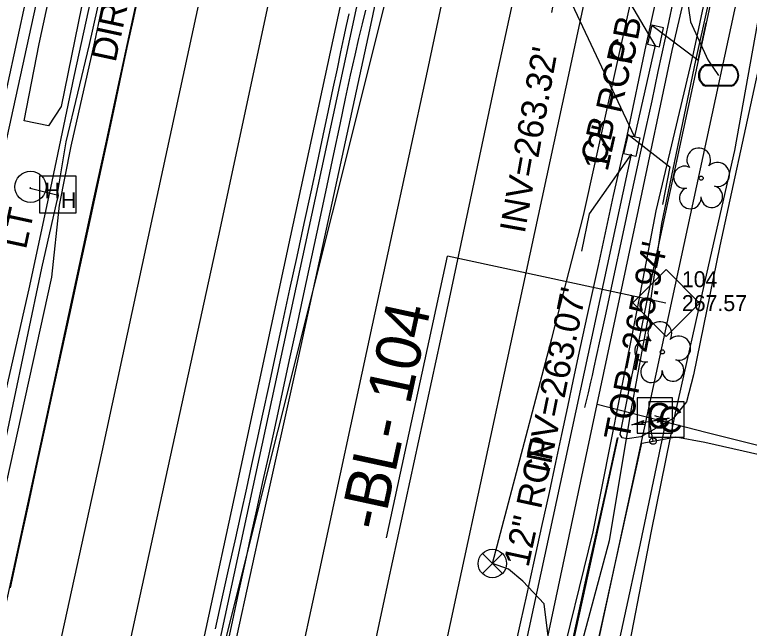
# Model space of a CAD drawing. Extents: x 2100323 to 2109811, y 740376 to 749755.
# Drawn here: x 2106040.1 to 2106155.4, y 743168.3 to 743264.5 of the extents above; entities that cross this region are included whole.
import ezdxf

# ---------------------------------------------------------------- set-up
doc = ezdxf.new("R2010")
doc.units = 0
for name, color, linetype in [('CTL Supplemental Horizontal and Vertical CELL', 7, 'Continuous'), ('CTL Supplemental Horizontal and Vertical Cogo Elevation', 7, 'Continuous'), ('CTL Supplemental Horizontal and Vertical Cogo Number', 7, 'Continuous'), ('Exist Building', 7, 'Continuous'), ('Exist Horizontal Alignment', 7, 'Continuous'), ('Exist Horizontal Baseline Alignment Station Label', 7, 'Continuous'), ('Exist Right of Way Line', 7, 'Continuous'), ('Exist Roads Change in Surface', 7, 'Continuous'), ('Exist Roads Curbs', 7, 'Continuous'), ('Exist Roads EOP', 7, 'Continuous'), ('Exist Roads EOP Other', 7, 'Continuous'), ('Exist Roads EOT', 7, 'Continuous'), ('Exist Structure Minor Catch Basin', 7, 'Continuous'), ('Exist Structure Minor Catch Basin Text', 7, 'Continuous'), ('Exist Structure Minor Catch Basin Top Elevation', 7, 'Continuous'), ('Exist Structure Minor Pipes RCP 12 Inch', 7, 'Continuous'), ('Exist Structure Minor Pipes RCP 12 Inch Invert', 7, 'Continuous'), ('Exist Structure Minor Pipes RCP 12 Inch Leader', 7, 'Continuous'), ('Exist Structure Minor Pipes RCP 12 Inch Text', 7, 'Continuous'), ('Exist Utilities Gas Change of Service SUE CELL', 7, 'Continuous'), ('Exist Utilities Gas UG Line SUE LOS B', 7, 'Continuous'), ('Exist Utilities Gas UG Line SUE LOS C', 7, 'Continuous'), ('Exist Utilities Other Pole CELL', 7, 'Continuous'), ('Exist Utilities Other Pole Text', 7, 'Continuous'), ('Exist Utilities Power Hand Hole CELL', 7, 'Continuous'), ('Exist Utilities Power UG Cable SUE LOS B', 7, 'Continuous'), ('Exist Utilities Telephone UG Conduit SUE LOS B', 7, 'Continuous'), ('Exist Utilities TV Pedestal CELL', 7, 'Continuous'), ('Exist Utilities TV UG Cable SUE LOS B', 7, 'Continuous'), ('Exist Utilities Water Meter CELL', 7, 'Continuous'), ('Exist Utilities Water UG Line SUE LOS B', 7, 'Continuous'), ('Exist Utilities Water UG Line SUE LOS C', 7, 'Continuous'), ('Exist Utilities Water Valve CELL', 7, 'Continuous'), ('Exist Vegetation Hedge Row', 7, 'Continuous'), ('Exist Vegetation Tree CELL', 7, 'Continuous')]:
    doc.layers.add(name, color=color, linetype=linetype)

msp = doc.modelspace()

# ---------------------------------------------------------------- linework, layer by layer
at = {"layer": 'CTL Supplemental Horizontal and Vertical CELL'}
msp.add_line((2106142.34, 743219.3), (2106142.34, 743219.3), dxfattribs=at)
msp.add_lwpolyline([(2106137.13, 743219.32), (2106142.37, 743224.56), (2106147.62, 743219.31), (2106142.38, 743214.07)], close=True, dxfattribs=at)
at = {"layer": 'Exist Building'}
msp.add_lwpolyline([(2106037.99, 743573.24), (2106018.9, 743485.96), (2106017.36, 743486.3), (2105996.61, 743391.41), (2105959.32, 743399.57), (2105929.35, 743262.52), (2106037.5, 743238.87), (2106107.3, 743558.09), (2106037.99, 743573.24)], dxfattribs=at)
at = {"layer": 'Exist Horizontal Alignment'}
msp.add_line((2106017.48, 742912.16), (2106313.31, 744282.7), dxfattribs=at)
at = {"layer": 'Exist Horizontal Baseline Alignment Station Label'}
for p in [(2106098.51, 743182.45), (2106142.34, 743219.3)]:
    msp.add_line(p, (2106108.06, 743226.69), dxfattribs=at)
at = {"layer": 'Exist Right of Way Line'}
for p, q in [((2106074.25, 742899.91), (2106310.88, 743996.15)), ((2105967.64, 742922.92), (2106195.83, 743980.08))]:
    msp.add_line(p, q, dxfattribs=at)
at = {"layer": 'Exist Roads Change in Surface'}
msp.add_lwpolyline([(2106126.61, 743160.71), (2106129.74, 743175), (2106134.86, 743198.21)], dxfattribs=at)
at = {"layer": 'Exist Roads Curbs'}
msp.add_lwpolyline([(2106143.36, 743266.32), (2106142.2, 743260.85), (2106141.09, 743255.65), (2106140.1, 743251.06), (2106139.19, 743246.87), (2106138.1, 743241.86), (2106136.79, 743235.85), (2106135.41, 743229.49), (2106134.1, 743223.4), (2106132.89, 743217.77), (2106131.98, 743213.55), (2106131.4, 743210.9), (2106131.03, 743209.23), (2106130.74, 743207.95), (2106130.5, 743206.92), (2106130.11, 743205.24), (2106129.57, 743202.91)], dxfattribs=at)
at = {"layer": 'Exist Roads EOP'}
for points in [[(2106118.63, 743165.04), (2106119.55, 743169.28), (2106120.49, 743173.46), (2106121.61, 743178.51), (2106122.88, 743184.24), (2106124.04, 743189.57), (2106125.06, 743194.3), (2106126, 743198.7), (2106126.92, 743203.01), (2106127.84, 743207.32), (2106128.89, 743212.18), (2106130.09, 743217.67), (2106131.73, 743225.2), (2106134.11, 743236.16), (2106136.23, 743245.52), (2106139.24, 743259.77), (2106142.15, 743273.03)], [(2106039.48, 743174.63), (2106040.84, 743180.94), (2106042.28, 743187.59), (2106043.67, 743194.05), (2106045.01, 743200.23), (2106046.32, 743206.31), (2106047.67, 743212.47), (2106049.04, 743218.74), (2106050.47, 743225.33), (2106051.97, 743232.27), (2106053.42, 743239.04), (2106054.73, 743245.08), (2106055.88, 743250.44), (2106056.91, 743255.21), (2106057.81, 743259.41), (2106058.71, 743263.59), (2106059.71, 743268.26)], [(2106071.65, 743168.2), (2106072.66, 743172.76), (2106073.69, 743177.43), (2106074.71, 743182.02), (2106075.66, 743186.3), (2106076.55, 743190.29), (2106077.37, 743193.99), (2106078.19, 743197.73), (2106079.09, 743201.85), (2106080.07, 743206.37), (2106081.12, 743211.27), (2106082.22, 743216.37), (2106083.33, 743221.49), (2106084.45, 743226.62), (2106085.57, 743231.77), (2106086.66, 743236.74), (2106087.66, 743241.36), (2106088.57, 743245.62), (2106089.4, 743249.51), (2106090.14, 743253.01), (2106090.79, 743256.08), (2106091.34, 743258.71), (2106091.8, 743260.9), (2106092.21, 743262.83), (2106092.62, 743264.66)], [(2106073.3, 743164.7), (2106074.31, 743169.27), (2106075.33, 743174), (2106076.35, 743178.69), (2106077.31, 743183.13), (2106078.23, 743187.33), (2106079.1, 743191.28), (2106079.95, 743195.12), (2106080.79, 743198.97), (2106081.64, 743202.84), (2106082.48, 743206.72), (2106083.38, 743210.87), (2106084.4, 743215.56), (2106085.53, 743220.78), (2106086.77, 743226.54), (2106088.02, 743232.36), (2106089.17, 743237.75), (2106090.23, 743242.74), (2106091.19, 743247.3), (2106092.06, 743251.42), (2106092.84, 743255.04), (2106093.55, 743258.18), (2106094.16, 743260.83), (2106094.71, 743263.14), (2106095.22, 743265.26)]]:
    msp.add_lwpolyline(points, dxfattribs=at)
at = {"layer": 'Exist Roads EOP Other'}
for points in [[(2105989.88, 742978.1), (2105992.89, 742991.26), (2106005.74, 743051.33), (2106017.11, 743104.36), (2106021.65, 743125.26), (2106026.92, 743151.57), (2106033.25, 743181.45), (2106042.52, 743222), (2106046.03, 743238.36), (2106049.46, 743254.83), (2106054.7, 743278.8), (2106061.75, 743311.36), (2106068.7, 743343.35), (2106074.92, 743372.78), (2106081.36, 743401.84), (2106085.54, 743420.55), (2106091.74, 743449.28), (2106096.24, 743470.29), (2106097.48, 743476.53)], [(2106080.8, 743366.85), (2106079.4, 743360.36), (2106077.85, 743353.14), (2106076.13, 743345.17), (2106074.26, 743336.46), (2106072.23, 743327.02), (2106070.21, 743317.61), (2106068.36, 743309.02), (2106066.69, 743301.24), (2106065.18, 743294.28), (2106063.85, 743288.13), (2106062.56, 743282.15), (2106061.16, 743275.67), (2106059.65, 743268.7), (2106058.04, 743261.24), (2106056.32, 743253.28), (2106054.48, 743244.73), (2106052.47, 743235.47), (2106050.32, 743225.5), (2106048, 743214.83), (2106045.53, 743203.45), (2106043.07, 743192.09), (2106040.77, 743181.48), (2106038.65, 743171.63)], [(2106161.39, 743276.68), (2106156.38, 743253.99), (2106150.81, 743228.26), (2106146.67, 743208.06), (2106145.55, 743203.82), (2106143.48, 743201.21), (2106138.4, 743198.33), (2106136.23, 743197.99), (2106135.49, 743198.14), (2106135.14, 743198.69), (2106140.27, 743224.09), (2106146.56, 743253.22), (2106151.11, 743274.45)], [(2106126.71, 743161.86), (2106129.94, 743176.57), (2106132.91, 743189.76), (2106134.76, 743198.15)]]:
    msp.add_lwpolyline(points, dxfattribs=at)
at = {"layer": 'Exist Roads EOT'}
for points in [[(2106042.22, 743015.09), (2106047.83, 743040.43), (2106053.82, 743067.44), (2106059.54, 743094.14), (2106064.45, 743117.21), (2106069.23, 743140.31), (2106072.98, 743157.65), (2106079.06, 743185.57), (2106084.46, 743209.75), (2106090.21, 743236.18), (2106095.86, 743262.17), (2106102.27, 743292.24), (2106107.53, 743316.8), (2106112.64, 743340.89), (2106118.09, 743366.19), (2106124.09, 743393.83), (2106130.04, 743422.38), (2106135.51, 743447.94), (2106140.44, 743471.17), (2106145.44, 743493.68), (2106154.86, 743537.27), (2106165.29, 743585.16)], [(2106137.18, 743582.93), (2106129.02, 743544.65), (2106120.52, 743506.04), (2106112.02, 743466.55), (2106104.11, 743429.36), (2106095.71, 743390.07), (2106086.87, 743348.78), (2106078.51, 743309.78), (2106070.2, 743271.79), (2106061.76, 743232.89), (2106053.82, 743195.96), (2106045.11, 743156.31), (2106036.83, 743117.88), (2106028.4, 743079), (2106020.18, 743040.87), (2106011.78, 743002.02)], [(2106146.94, 743578.03), (2106138.92, 743540.77), (2106130.66, 743502.58), (2106122.28, 743464.49), (2106113.88, 743424.79), (2106105.83, 743386.93), (2106097.43, 743347.7), (2106089.21, 743309.26), (2106080.88, 743270.71), (2106072.32, 743230.86), (2106063.87, 743192.12), (2106055.42, 743153.43), (2106047.06, 743115.78), (2106038.73, 743077.35), (2106030.31, 743038.03), (2106021.98, 742999.54)], [(2106158.44, 743577.13), (2106150.88, 743543.06), (2106141.86, 743501.64), (2106133.69, 743463.5), (2106125.22, 743424.34), (2106117.02, 743385.24), (2106108.57, 743346.18), (2106100.3, 743308.18), (2106092.15, 743270.35), (2106083.38, 743229.64), (2106074.58, 743188.81), (2106066.53, 743151.58), (2106058.54, 743114.96), (2106050.08, 743075.72), (2106041.09, 743034.02), (2106033.02, 742996.93)], [(2106171.45, 743565.7), (2106162.92, 743526.09), (2106154.45, 743487.7), (2106146.46, 743449.9), (2106138.49, 743412.94), (2106129.21, 743369.77), (2106121.28, 743332.76), (2106113.24, 743295.18), (2106104.84, 743255.68), (2106096.26, 743215.86), (2106087.79, 743176.73), (2106079.4, 743137.92), (2106071.31, 743101.11), (2106063, 743062.7), (2106054.24, 743022.2)], [(2106193.66, 743565.28), (2106185.3, 743526.87), (2106176.78, 743487.84), (2106168.56, 743449.4), (2106160.38, 743411.11), (2106152.2, 743372.73), (2106144.04, 743334.47), (2106135.63, 743295.17), (2106126.64, 743253.17), (2106117.92, 743212.89), (2106109.67, 743174.65), (2106101.11, 743134.7), (2106092.9, 743096.54), (2106084.52, 743058.41), (2106075.56, 743016.95)], [(2106182.44, 743563.86), (2106174.23, 743526.18), (2106165.71, 743486.89), (2106157.44, 743448.87), (2106149.13, 743409.72), (2106140.41, 743369.02), (2106132.02, 743330.94), (2106124, 743292.93), (2106115.66, 743254.49), (2106107.57, 743216.53), (2106098.74, 743175.74), (2106090.58, 743137.61), (2106082.3, 743099.34), (2106073.69, 743059.33), (2106064.38, 743016.38)]]:
    msp.add_lwpolyline(points, dxfattribs=at)
at = {"layer": 'Exist Structure Minor Catch Basin'}
for points in [[(2106141.3, 743259.52), (2106141.95, 743262.49), (2106140.11, 743262.89), (2106139.46, 743259.92)], [(2106138.24, 743245.23), (2106137.59, 743242.32), (2106135.73, 743242.74), (2106136.39, 743245.65)]]:
    msp.add_lwpolyline(points, close=True, dxfattribs=at)
at = {"layer": 'Exist Structure Minor Catch Basin Top Elevation'}
for points in [[(2106140.11, 743262.88), (2106147.4, 743257.4), (2106148.64, 743263.27)], [(2106136.34, 743245.78), (2106142.96, 743240.68), (2106141.8, 743234.79)]]:
    msp.add_lwpolyline(points, dxfattribs=at)
at = {"layer": 'Exist Structure Minor Pipes RCP 12 Inch'}
for p, q in [((2106140.62, 743259.77), (2106137.42, 743245.42)), ((2106136.88, 743242.67), (2106098.45, 743064.44))]:
    msp.add_line(p, q, dxfattribs=at)
at = {"layer": 'Exist Structure Minor Pipes RCP 12 Inch Leader'}
for points in [[(2106137.42, 743245.42), (2106125.46, 743270.8), (2106124.39, 743264.9)], [(2106140.62, 743259.77), (2106136.13, 743267.43), (2106136.47, 743269.02)], [(2106136.88, 743242.67), (2106130.27, 743233.32), (2106129.07, 743227.44)]]:
    msp.add_lwpolyline(points, dxfattribs=at)
at = {"layer": 'Exist Utilities Gas Change of Service SUE CELL'}
for p, q in [((2106142.86, 743201.25), (2106136.99, 743200.2)), ((2106139.77, 743200.7), (2106142.86, 743201.25)), ((2106140.31, 743197.66), (2106139.77, 743200.7)), ((2106140.31, 743197.66), (2106140.31, 743197.66))]:
    msp.add_line(p, q, dxfattribs=at)
for points in [[(2106142.86, 743201.25), (2106140.98, 743200.57), (2106141.33, 743200.98), (2106140.9, 743201.21)], [(2106136.99, 743200.2), (2106138.87, 743200.89), (2106138.51, 743200.47), (2106138.94, 743200.24)]]:
    msp.add_lwpolyline(points, close=True, dxfattribs=at)
msp.add_circle((2106140.31, 743197.66), 0.517, dxfattribs=at)
at = {"layer": 'Exist Utilities Gas UG Line SUE LOS B'}
msp.add_lwpolyline([(2106140.31, 743197.66), (2106143.88, 743198.31), (2106148.46, 743197.48), (2106192.36, 743187.57), (2106207.21, 743185.29), (2106222.26, 743181.85), (2106233.55, 743180.98), (2106241.94, 743181.9), (2106247.4, 743184.25)], dxfattribs=at)
at = {"layer": 'Exist Utilities Gas UG Line SUE LOS C'}
msp.add_lwpolyline([(2106064.67, 742860.19), (2106069.59, 742879.36), (2106086.29, 742957.89), (2106098.56, 743010.84), (2106112.62, 743079.76), (2106138.57, 743197.35), (2106140.31, 743197.66)], dxfattribs=at)
at = {"layer": 'Exist Utilities Other Pole CELL'}
msp.add_circle((2106042.62, 743237.54), 2.46, dxfattribs=at)
at = {"layer": 'Exist Utilities Power Hand Hole CELL'}
msp.add_line((2106046.99, 743236.2), (2106046.99, 743236.2), dxfattribs=at)
msp.add_lwpolyline([(2106044.04, 743233.47), (2106049.79, 743233.47), (2106049.79, 743239.22), (2106044.04, 743239.22), (2106044.04, 743233.47)], dxfattribs=at)
at = {"layer": 'Exist Utilities Power UG Cable SUE LOS B'}
for points in [[(2106046.99, 743236.2), (2106046.92, 743236.77), (2106048.23, 743244.61), (2106051.85, 743259.85), (2106058.03, 743287.41), (2106062.68, 743310.27), (2106066.47, 743326.61), (2106068.59, 743337.33), (2106074.88, 743361.82), (2106076.79, 743376.2), (2106078.79, 743383.74), (2106081.19, 743394.01), (2106081.35, 743394.88), (2106080.32, 743395.02), (2106077.01, 743395.65), (2106076.86, 743395.66)], [(2106078.42, 743380.17), (2106078.04, 743377.85), (2106074.52, 743362.69), (2106069.27, 743337.24), (2106067.38, 743327.27), (2106061.4, 743310.77), (2106058.61, 743288.6), (2106052.66, 743260.3), (2106048.94, 743243.92), (2106047.1, 743234.64), (2106045.92, 743223.36), (2106038.78, 743191.03), (2106034.86, 743175.39), (2106030.52, 743155.65), (2106029.65, 743154.26)], [(2106094.23, 743016.65), (2106098.81, 743040.21), (2106103.37, 743060.13), (2106106.75, 743074.8), (2106112.98, 743104.04), (2106117.89, 743128.72), (2106120.32, 743138.55), (2106121.45, 743145.59), (2106122.31, 743148.82), (2106125.2, 743160.21), (2106130.9, 743183.42), (2106137.89, 743218.46), (2106140.82, 743233.8), (2106146.65, 743258.46), (2106151.21, 743279.92), (2106156.39, 743299.99), (2106156.84, 743301.79)], [(2106128, 743161.62), (2106133.5, 743182.08), (2106136.92, 743202.71), (2106139.59, 743217.17), (2106141.7, 743231.8), (2106147.04, 743257.37), (2106150.69, 743273.82), (2106152.6, 743281.09), (2106154.87, 743290.32), (2106155.9, 743291.18), (2106155.23, 743291.59), (2106155.71, 743295.79), (2106156.71, 743299.84), (2106156.84, 743301.79), (2106157.69, 743301.38), (2106160.23, 743300.55), (2106162.62, 743297.85)], [(2106127.24, 743143.85), (2106128.32, 743143.14), (2106130.45, 743145.28), (2106132.42, 743151.09), (2106135.43, 743159.46), (2106140.07, 743183.51), (2106143.83, 743202.07), (2106148.81, 743224.15), (2106153.14, 743243.22), (2106157.68, 743268.66), (2106160.13, 743282.88), (2106161.79, 743295.06), (2106162.62, 743297.85)], [(2106021.82, 743118.35), (2106021.8, 743119.15), (2106026.94, 743145.86), (2106029.69, 743157.25), (2106033.91, 743175.01), (2106037.29, 743191.19), (2106044.4, 743224.78), (2106046.82, 743235.41), (2106046.99, 743236.2), (2106046.14, 743236.38), (2106042.59, 743237.29), (2106042.64, 743237.49)]]:
    msp.add_lwpolyline(points, dxfattribs=at)
at = {"layer": 'Exist Utilities Telephone UG Conduit SUE LOS B'}
for points in [[(2106086.38, 742995.86), (2106097.58, 743046.43), (2106104.1, 743075.32), (2106115.52, 743129.19), (2106122.57, 743161.02), (2106131.54, 743203.47), (2106138.01, 743233.94), (2106143.33, 743258.94), (2106148.33, 743280.51)], [(2106131.54, 743203.47), (2106148.81, 743199.01), (2106192.13, 743188.16), (2106207.68, 743184.44), (2106211.82, 743184.37), (2106213.24, 743186.14), (2106214.3, 743188.57), (2106214.93, 743191.07)]]:
    msp.add_lwpolyline(points, dxfattribs=at)
at = {"layer": 'Exist Utilities TV Pedestal CELL'}
for p, q in [((2106140.59, 743201.64), (2106140.59, 743201.64)), ((2106142.43, 743201.05), (2106142.43, 743201.05))]:
    msp.add_line(p, q, dxfattribs=at)
for points in [[(2106137.81, 743198.87), (2106143.36, 743198.87), (2106143.36, 743204.42), (2106137.81, 743204.42), (2106137.81, 743198.87)], [(2106139.66, 743198.28), (2106145.21, 743198.28), (2106145.21, 743203.83), (2106139.66, 743203.83), (2106139.66, 743198.28)]]:
    msp.add_lwpolyline(points, dxfattribs=at)
at = {"layer": 'Exist Utilities TV UG Cable SUE LOS B'}
msp.add_lwpolyline([(2106104.33, 743022.68), (2106109.86, 743044.21), (2106114.03, 743071.01), (2106120.9, 743102.04), (2106125.34, 743120.47), (2106131.18, 743142.67), (2106133.66, 743159.9), (2106138.14, 743180.61), (2106142.43, 743201.05), (2106140.59, 743201.64)], dxfattribs=at)
at = {"layer": 'Exist Utilities Water Meter CELL'}
msp.add_line((2106150.61, 743255.02), (2106150.61, 743255.02), dxfattribs=at)
for points in [[(2106148.57, 743256.72), (2106152.65, 743256.72)], [(2106148.57, 743256.58), (2106152.65, 743256.58)], [(2106152.65, 743253.45), (2106148.55, 743253.45)], [(2106152.65, 743253.32), (2106148.55, 743253.32)]]:
    msp.add_lwpolyline(points, dxfattribs=at)
for centre, radius, start, end in [((2106149.3, 743255.01), 1.86, 113.178, 245.9794), ((2106149.31, 743255.01), 1.73, 115.3009, 243.7824), ((2106151.9, 743255.02), 1.86, 293.6483, 66.3084), ((2106151.92, 743255.02), 1.73, 295.1272, 64.8728)]:
    msp.add_arc(centre, radius, start, end, dxfattribs=at)
at = {"layer": 'Exist Utilities Water UG Line SUE LOS B'}
for points in [[(2106115.11, 743178.44), (2106124.41, 743213.73), (2106129.4, 743233.04), (2106138.74, 743275.37), (2106140.55, 743277.4), (2106143.2, 743273.92), (2106145.21, 743270.29), (2106146.2, 743263.42), (2106148.93, 743257.45), (2106150.61, 743255.02)], [(2106127.76, 743150.81), (2106124.83, 743161.41), (2106123.9, 743166.63), (2106123.25, 743172.14), (2106119.89, 743175.67), (2106117.62, 743177.57), (2106115.11, 743178.44)]]:
    msp.add_lwpolyline(points, dxfattribs=at)
at = {"layer": 'Exist Utilities Water UG Line SUE LOS C'}
msp.add_line((2106057.69, 743104.45), (2106103.68, 743287.99), dxfattribs=at)
at = {"layer": 'Exist Utilities Water Valve CELL'}
msp.add_lwpolyline([(2106116.68, 743180.01), (2106113.53, 743176.86), (2106115.1, 743178.44), (2106116.68, 743176.86), (2106113.53, 743180.01)], dxfattribs=at)
msp.add_circle((2106115.1, 743178.44), 2.23, dxfattribs=at)
at = {"layer": 'Exist Vegetation Hedge Row'}
msp.add_lwpolyline([(2106053.87, 743281.75), (2106047.41, 743250.16), (2106045.45, 743247.13), (2106041.6, 743247.88), (2106043.97, 743260), (2106052.48, 743299.42), (2106059.66, 743333.14), (2106067.11, 743366.13), (2106070.73, 743384.4), (2106073.49, 743387.85), (2106076.65, 743384.96), (2106071.34, 743360.46), (2106064.8, 743329.82), (2106053.87, 743281.75)], dxfattribs=at)
at = {"layer": 'Exist Vegetation Tree CELL'}
for p, q in [((2106147.86, 743238.9), (2106147.86, 743238.9)), ((2106141.77, 743211.65), (2106141.77, 743211.65))]:
    msp.add_line(p, q, dxfattribs=at)
for centre in [(2106147.86, 743238.9), (2106141.77, 743211.65)]:
    msp.add_circle(centre, 0.326, dxfattribs=at)
for centre, radius, start, end in [((2106147.48, 743241.77), 1.86, 330.1651, 219.7134), ((2106145.26, 743239.05), 1.73, 62.6636, 279.3457), ((2106150.41, 743239.48), 1.9, 257.1011, 134.1999), ((2106146.16, 743235.78), 1.69, 111.5671, 6.231), ((2106149.53, 743236), 1.7, 181.2822, 74.56), ((2106141.38, 743214.53), 1.86, 330.1651, 219.7134), ((2106144.32, 743212.24), 1.9, 257.1011, 134.1999), ((2106139.16, 743211.81), 1.73, 62.6636, 279.3457), ((2106140.06, 743208.53), 1.69, 111.5671, 6.231), ((2106143.44, 743208.75), 1.7, 181.2822, 74.56)]:
    msp.add_arc(centre, radius, start, end, dxfattribs=at)

# ---------------------------------------------------------------- texts
at = {"layer": 'CTL Supplemental Horizontal and Vertical Cogo Elevation'}
msp.add_text('267.57', height=2.5, dxfattribs=at).set_placement((2106144.84, 743218.05))
at = {"layer": 'CTL Supplemental Horizontal and Vertical Cogo Number'}
msp.add_text('104', height=2.5, dxfattribs=at).set_placement((2106144.84, 743221.8))
at = {"layer": 'Exist Horizontal Baseline Alignment Station Label'}
msp.add_text('-BL- 104  ', height=7, rotation=77.8136, dxfattribs=at).set_placement((2106097.87, 743183.38))
at = {"layer": 'Exist Structure Minor Catch Basin Text'}
for rotation, p in [(79.1974, (2106137.17, 743256.6)), (77.233, (2106132.76, 743240.76))]:
    msp.add_text('CB', height=4, rotation=rotation, dxfattribs=at).set_placement(p)
at = {"layer": 'Exist Structure Minor Catch Basin Top Elevation'}
msp.add_text("TOP=265.94'", height=4, rotation=78.8596, dxfattribs=at).set_placement((2106136.5, 743197.53))
at = {"layer": 'Exist Structure Minor Pipes RCP 12 Inch Invert'}
for s, rotation, p in [('DIR ONLY', 77.9403, (2106055.96, 743256.95)), ("INV=263.32'", 79.7893, (2106120.16, 743230.09)), ("INV=263.07'", 78.5152, (2106124, 743192.43))]:
    msp.add_text(s, height=4, rotation=rotation, dxfattribs=at).set_placement(p)
at = {"layer": 'Exist Structure Minor Pipes RCP 12 Inch Text'}
for rotation, p in [(77.4247, (2106133.17, 743239.84)), (77.8332, (2106120.75, 743177.72))]:
    msp.add_text('12" RCP', height=4, rotation=rotation, dxfattribs=at).set_placement(p)
at = {"layer": 'Exist Utilities Other Pole Text'}
msp.add_text('LT', height=4, rotation=77.8136, dxfattribs=at).set_placement((2106041.9, 743227.61))
at = {"layer": 'Exist Utilities Power Hand Hole CELL'}
for p in [(2106044.83, 743235.72), (2106047.39, 743234.2)]:
    msp.add_text('H', height=2.5, dxfattribs=at).set_placement(p)
at = {"layer": 'Exist Utilities TV Pedestal CELL'}
for p in [(2106139.28, 743199.64), (2106141.12, 743199.05)]:
    msp.add_text('C', height=4, dxfattribs=at).set_placement(p)

doc.saveas('drawing.dxf')
